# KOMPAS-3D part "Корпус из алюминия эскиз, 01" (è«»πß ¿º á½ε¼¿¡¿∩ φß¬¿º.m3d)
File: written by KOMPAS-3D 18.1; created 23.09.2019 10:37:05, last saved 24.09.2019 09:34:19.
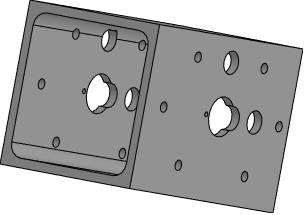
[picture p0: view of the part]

Document properties: Полное имя файла: D:\Мембранные насосы\Мембранный электропривод\А302-00.00.000 - ASTRA-302 (МЭ200)\3Д ПВХ\Копус из алюминия эскиз.m3d

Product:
- Part/product: Корпус из алюминия эскиз  | designation 01
    Материал: Д16  ГОСТ 4784-97 (density 2800 kg/m3)
    Масса: 2.31286
- Part/product: Корпус из алюминия эскиз
    Материал: Д16  ГОСТ 4784-97 (density 2800 kg/m3)
    Масса: 2.31286

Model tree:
1. Эскиз:4  (with: Операция выдавливания:1)  (labels: Мотор-редуктор\Фланец\Труба 140х140х4; А302-01.05.000 - Корпус.a3d)
2. Элемент выдавливания:1
     Расстояние 2 = 265
3. Эскиз:8  (with: Операция выдавливания:1, Элемент выдавливания:1)
4. Элемент выдавливания:2
     Расстояние 2 = 20
5. Эскиз:10  (with: Вырезать элемент выдавливания:1, Вырезать элемент выдавливания:6, Вырезать элемент выдавливания:7, Вырезать элемент выдавливания:8, Вырезать элемент выдавливания:10, Фаска:1)  (labels: Мотор-редуктор\Фланец\Труба 140х140х4)
6. Эскиз:12  (with: Вырезать элемент выдавливания:1, Вырезать элемент выдавливания:6, Вырезать элемент выдавливания:7, Вырезать элемент выдавливания:8, Вырезать элемент выдавливания:10, Фаска:1)  (labels: Мотор-редуктор\Фланец\Труба 140х140х4)
7. Скругление:2  (with: Элемент выдавливания:1)
     Радиус = 12
8. Элемент выдавливания:6
     Расстояние 2 = 10
9. Элемент выдавливания:7
     Расстояние 2 = 10
10. Эскиз:14  (with: Элемент выдавливания:1, Вырезать элемент выдавливания:9)  (labels: Мотор-редуктор\Фланец\Труба 140х140х4)
11. Элемент выдавливания:8
     Расстояние 2 = 18
12. Скругление:1  (with: Элемент выдавливания:1)
     Радиус = 6
13. Эскиз:15  (with: Элемент выдавливания:1, Скругление:1)
14. Эскиз:17  (with: Элемент выдавливания:2, Элемент выдавливания:1, Скругление:1)
15. Элемент выдавливания:12
     Расстояние 1 = 116.5
16. Элемент выдавливания:13  (with: Элемент выдавливания:1)
     Расстояние 2 = 56
17. Эскиз:19  (with: Элемент выдавливания:2, Элемент выдавливания:1, Скругление:2)
18. Элемент выдавливания:14
     Расстояние 2 = 51
19. Эскиз:21  (with: Элемент выдавливания:1, Скругление:2)
20. Элемент выдавливания:15
     Расстояние 2 = 265
21. Элемент выдавливания:16  (with: Элемент выдавливания:13)
     Расстояние 2 = 10
22. Элемент выдавливания:17  (with: Элемент выдавливания:1)
     Расстояние 2 = 56
23. Элемент выдавливания:18  (with: Элемент выдавливания:17)  (labels: Д16  ГОСТ 4784-97; А302-01.05.000 - Корпус.a3d)
     Расстояние 2 = 10
24. Элемент выдавливания:19  (with: Элемент выдавливания:1)  (labels: Д16  ГОСТ 4784-97)
     Расстояние 2 = 12

Referenced files in D:\Мембранные насосы\Мембранный электропривод\А302-00.00.000 - ASTRA-302 (МЭ200)\3Д ПВХ\: А302-01.05.000 - Корпус.a3d
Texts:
  Копус из алюминия эскиз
